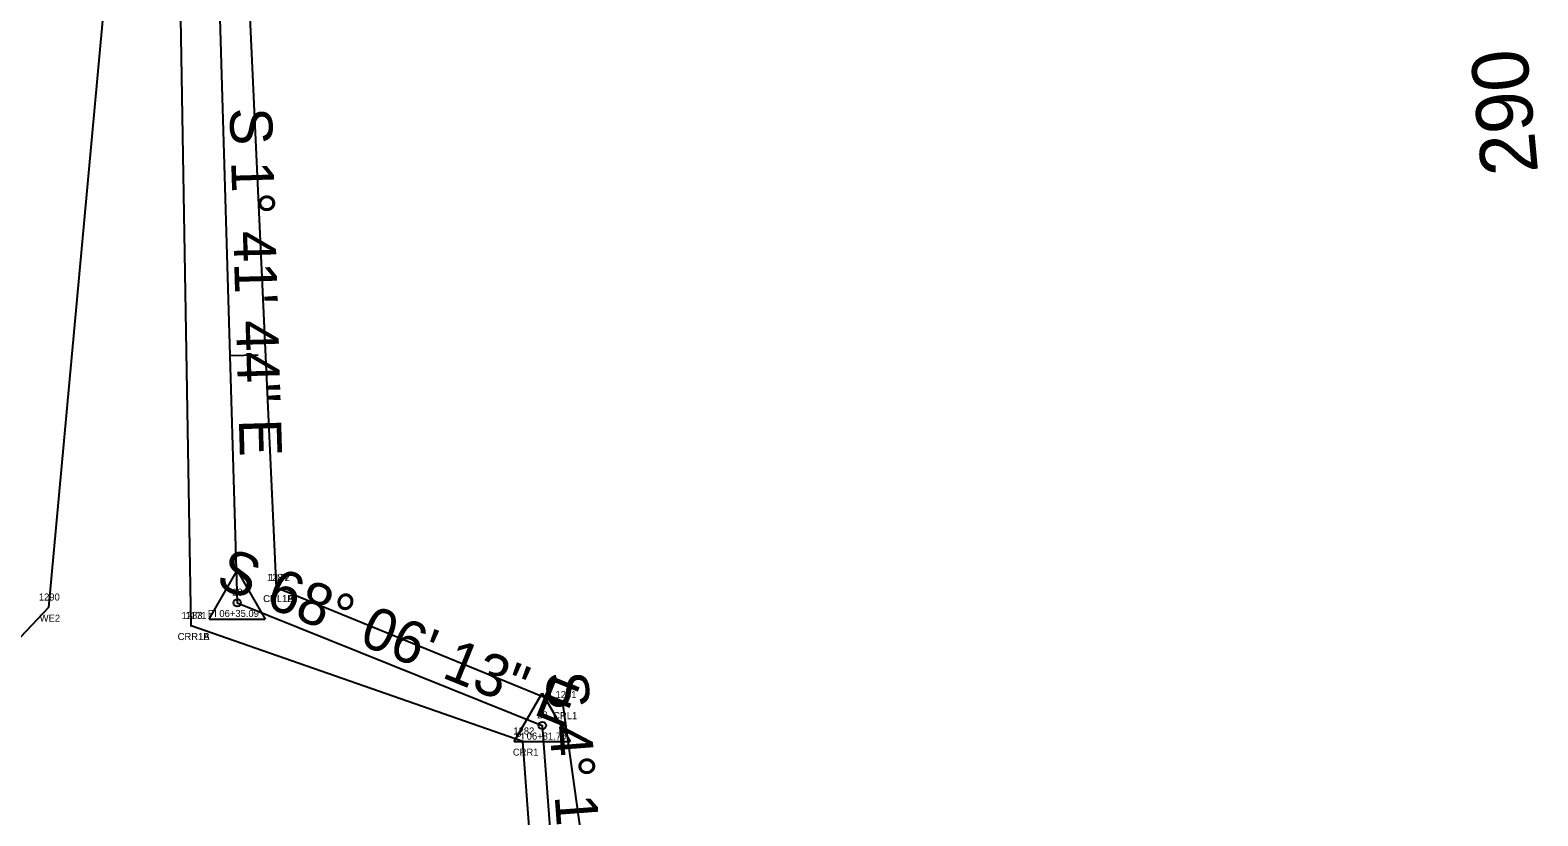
# Model space of a CAD drawing. Extents: x 2445178 to 2446205, y 790762 to 792372.
# Drawn here: x 2445380.3 to 2445594.3, y 791793.8 to 791905.3 of the extents above; entities that cross this region are included whole.
import ezdxf

# ---------------------------------------------------------------- set-up
doc = ezdxf.new("R2010")
doc.units = 0
for name, color, linetype in [('RD_EX_H2O', 7, 'Continuous'), ('RD_EX_H2O_txCode', 7, 'Continuous'), ('RD_HC_Cl', 7, 'Continuous'), ('RD_HC_Data', 7, 'Continuous'), ('RD_HC_Data_Tic', 7, 'Continuous'), ('RD_HC_TX_Sta50', 7, 'Continuous'), ('RD_HC_txCode', 7, 'Continuous'), ('RD_SMD_Locator', 7, 'Continuous')]:
    doc.layers.add(name, color=color, linetype=linetype)

msp = doc.modelspace()

# ---------------------------------------------------------------- linework, layer by layer
at = {"layer": 'RD_EX_H2O'}
for points in [[(2445415.21, 791826.15), (2445411.13, 791915.36), (2445401.26, 791978.48), (2445346.75, 792066.4), (2445347.89, 792130.96), (2445327.72, 792154.04), (2445265.04, 792188.92)], [(2445403.09, 791820.76), (2445401.57, 791912.69), (2445385.3, 791968.86), (2445336.54, 792059.75), (2445337.52, 792129.63), (2445324.7, 792141.79), (2445250.6, 792162.62)], [(2445390.88, 791910.3), (2445382.88, 791823.37), (2445332.21, 791769.8), (2445259.4, 791752.08), (2445179.59, 791723.55)], [(2445544.99, 791749.08), (2445517.8, 791768.36), (2445478.59, 791760.86), (2445463.48, 791763.9), (2445460.87, 791773.93), (2445455.89, 791809.54), (2445415.21, 791826.15)], [(2445530.12, 791747.41), (2445515.88, 791756.64), (2445479.19, 791754.53), (2445461.81, 791756.69), (2445452.6, 791771.81), (2445450.18, 791804.36), (2445403.09, 791820.76)]]:
    msp.add_lwpolyline(points, dxfattribs=at)
at = {"layer": 'RD_HC_Cl'}
for p, q in [((2445406.98, 791914.3), (2445409.65, 791824.04)), ((2445409.65, 791824.04), (2445452.95, 791806.64)), ((2445452.95, 791806.64), (2445455.58, 791771.48))]:
    msp.add_line(p, q, dxfattribs=at)
at = {"layer": 'RD_HC_Data'}
for p, q in [((2445405.68, 791821.75), (2445409.65, 791828.63)), ((2445409.65, 791828.63), (2445413.62, 791821.75)), ((2445405.68, 791821.75), (2445413.62, 791821.75)), ((2445448.98, 791804.35), (2445452.95, 791811.23)), ((2445452.95, 791811.23), (2445456.92, 791804.35)), ((2445448.98, 791804.35), (2445456.92, 791804.35))]:
    msp.add_line(p, q, dxfattribs=at)
for centre in [(2445409.65, 791824.04), (2445452.95, 791806.64)]:
    msp.add_circle(centre, 0.529, dxfattribs=at)
at = {"layer": 'RD_HC_Data_Tic'}
msp.add_line((2445408.61, 791859.12), (2445412.61, 791859.23), dxfattribs=at)
at = {"layer": 'RD_SMD_Locator'}
for centre in [(2445415.21, 791826.15), (2445415.21, 791826.15), (2445382.88, 791823.37), (2445409.65, 791824.04), (2445403.09, 791820.76), (2445403.09, 791820.76), (2445455.89, 791809.54), (2445452.95, 791806.64), (2445450.18, 791804.36)]:
    msp.add_circle(centre, 0.001, dxfattribs=at)

# ---------------------------------------------------------------- texts
at = {"layer": 'RD_EX_H2O_txCode'}
for s, p in [('1284', (2445413.87, 791827.15)), ('1172', (2445414.15, 791827.15)), ('1290', (2445381.49, 791824.37)), ('CRL1A', (2445413.33, 791824.15)), ('CRL1B', (2445413.35, 791824.15)), ('WE2', (2445381.61, 791821.37)), ('1283', (2445401.75, 791821.76)), ('1171', (2445402.31, 791821.76)), ('CRR1A', (2445401.19, 791818.76)), ('CRR1B', (2445401.2, 791818.76)), ('1281', (2445454.82, 791810.54)), ('CRL1', (2445454.49, 791807.54)), ('1282', (2445448.84, 791805.36)), ('CRR1', (2445448.77, 791802.36))]:
    msp.add_text(s, height=1, dxfattribs=at).set_placement(p)
at = {"layer": 'RD_HC_Data'}
for s, rotation, p in [('S 1%%d 41\' 44" E', 271.6956, (2445408.57, 791894.23)), ('S 68%%d 06\' 13" E', 338.1035, (2445406.39, 791826.43)), ('S 4%%d 17\' 05" E', 274.2847, (2445453.39, 791814.11))]:
    msp.add_text(s, height=6, rotation=rotation, dxfattribs=at).set_placement(p)
at = {"layer": 'RD_HC_TX_Sta50'}
msp.add_text('290', height=8, rotation=95.3186, dxfattribs=at).set_placement((2445594.3, 791885.11))
at = {"layer": 'RD_HC_txCode'}
for s, p in [('28', (2445408.92, 791825.04)), ('PI 06+35.09', (2445405.48, 791822.04)), ('29', (2445452.22, 791807.64)), ('PI 06+81.75', (2445449.1, 791804.64))]:
    msp.add_text(s, height=1, dxfattribs=at).set_placement(p)

doc.saveas('drawing.dxf')
